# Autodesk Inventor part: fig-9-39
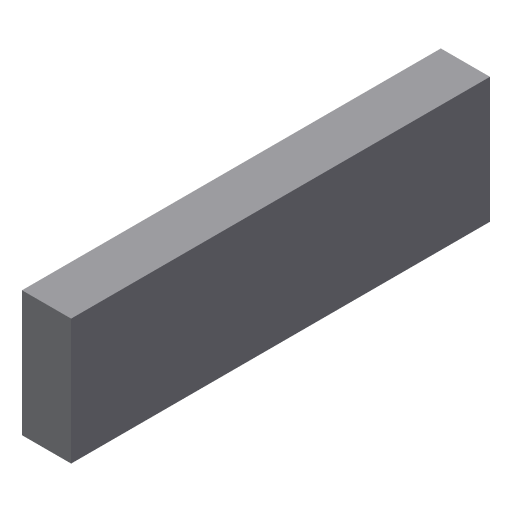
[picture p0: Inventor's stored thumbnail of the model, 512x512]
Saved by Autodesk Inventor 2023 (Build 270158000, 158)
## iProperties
Created: 2013-03
Part Number: fig-9-39
Material: Generic
Document SubType Name: Modeling
Designer: CADCIM
Density: 1 g/cm^3
Appearance: Default
Author: CADCIM
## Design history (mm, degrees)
sketch "Sketch1"
  geometry: L1 (-11.87, 2.655)-(7.31, 2.655); L2 (7.31, 2.655)-(7.31, -3.093); L3 (7.31, -3.093)-(-11.87, -3.093); L4 (-11.87, -3.093)-(-11.87, 2.655); 1 further point
  constraints: 8 end point, 2 parallel, 1 horizontal, 1 perpendicular
extrude "Extrusion1" new body sketch "Sketch1" distance "d0" = 2.25; taper "d1" = 0 deg
body "Solid1"
